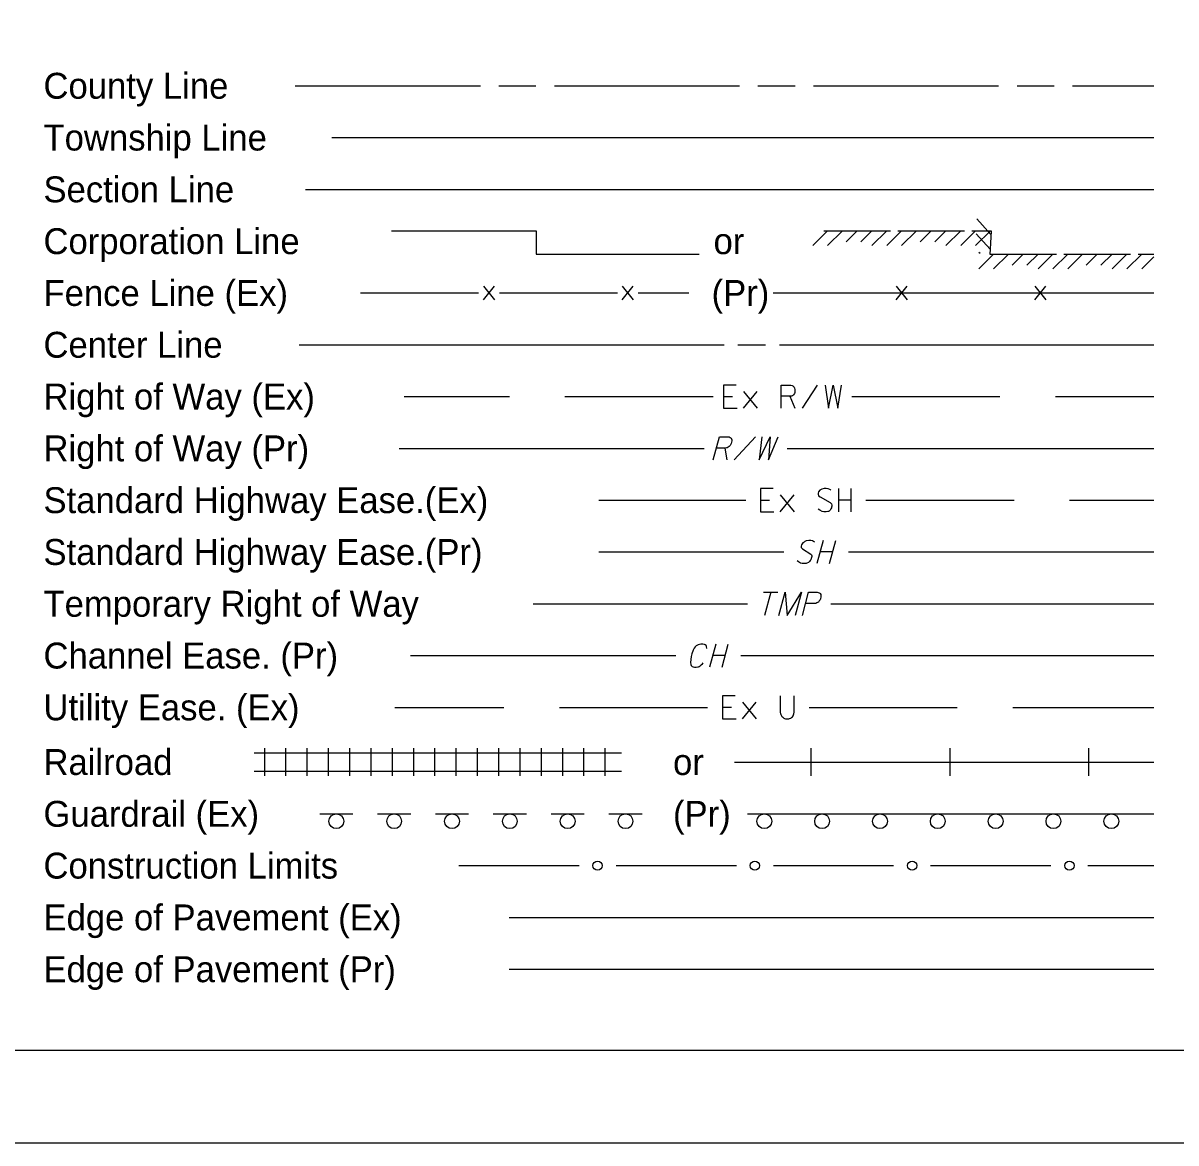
# Model space of a CAD drawing. Extents: x -19 to 40.8, y -1.8 to 26.1.
# Drawn here: x 1.61 to 7.84, y 0 to 6.05 of the extents above; entities that cross this region are included whole.
import ezdxf

# ---------------------------------------------------------------- set-up
doc = ezdxf.new("R2010")
doc.units = 0
for name, color, linetype in [('SH_Border', 7, 'Continuous'), ('SH_Cut_Line', 7, 'Continuous'), ('SH_Text', 7, 'Continuous')]:
    doc.layers.add(name, color=color, linetype=linetype)

msp = doc.modelspace()

# ---------------------------------------------------------------- linework, layer by layer
at = {"layer": 'SH_Border'}
msp.add_lwpolyline([(1.5, 21.5), (33.5, 21.5), (33.5, 0.5), (1.5, 0.5)], close=True, dxfattribs=at)
at = {"layer": 'SH_Cut_Line'}
msp.add_lwpolyline([(0, 0), (34, 0), (34, 22), (0, 22)], close=True, dxfattribs=at)
at = {"layer": 'SH_Text'}
for p, q in [((3.0856, 5.7144), (4.0856, 5.7144)), ((4.1856, 5.7144), (4.3856, 5.7144)), ((4.4856, 5.7144), (5.4856, 5.7144)), ((5.5856, 5.7144), (5.7856, 5.7144)), ((5.8856, 5.7144), (6.8856, 5.7144)), ((6.9856, 5.7144), (7.1856, 5.7144)), ((7.2856, 5.7144), (7.7247, 5.7144)), ((3.2837, 5.4344), (7.7247, 5.4344)), ((3.141, 5.1544), (7.7247, 5.1544)), ((6.844, 4.9108), (6.7678, 4.9945)), ((3.6051, 4.9308), (4.3876, 4.9308)), ((4.3876, 4.9308), (4.3876, 4.8044)), ((5.9614, 4.9308), (5.8814, 4.8508)), ((5.9414, 4.9308), (6.0414, 4.9308)), ((6.0414, 4.9308), (5.9614, 4.8508)), ((6.0414, 4.9308), (6.1214, 4.9308)), ((6.1214, 4.9308), (6.0614, 4.8708)), ((6.1214, 4.9308), (6.2014, 4.9308)), ((6.2014, 4.9308), (6.1414, 4.8708)), ((6.2014, 4.9308), (6.3014, 4.9308)), ((6.2814, 4.9308), (6.2014, 4.8508)), ((6.3614, 4.9308), (6.2814, 4.8508)), ((6.3414, 4.9308), (6.4414, 4.9308)), ((6.4414, 4.9308), (6.3614, 4.8508)), ((6.4414, 4.9308), (6.5214, 4.9308)), ((6.5214, 4.9308), (6.4614, 4.8708)), ((6.5214, 4.9308), (6.6014, 4.9308)), ((6.6014, 4.9308), (6.5414, 4.8708)), ((6.6014, 4.9308), (6.7014, 4.9308)), ((6.6814, 4.9308), (6.6014, 4.8508)), ((6.7614, 4.9308), (6.6814, 4.8508)), ((6.7414, 4.9308), (6.8414, 4.9308)), ((6.8414, 4.9308), (6.7614, 4.8508)), ((6.8449, 4.9308), (6.8403, 4.8309)), ((6.8414, 4.9308), (6.8449, 4.9308)), ((6.8403, 4.8309), (6.7641, 4.9145)), ((4.3876, 4.8044), (5.2686, 4.8044)), ((6.859, 4.8044), (6.779, 4.7244)), ((6.7857, 4.8069), (6.7794, 4.8137)), ((6.8403, 4.8309), (6.839, 4.8044)), ((6.839, 4.8044), (6.939, 4.8044)), ((6.939, 4.8044), (6.859, 4.7244)), ((6.939, 4.8044), (7.019, 4.8044)), ((7.019, 4.8044), (6.959, 4.7444)), ((7.019, 4.8044), (7.099, 4.8044)), ((7.099, 4.8044), (7.039, 4.7444)), ((7.099, 4.8044), (7.199, 4.8044)), ((7.179, 4.8044), (7.099, 4.7244)), ((7.259, 4.8044), (7.179, 4.7244)), ((7.239, 4.8044), (7.339, 4.8044)), ((7.339, 4.8044), (7.259, 4.7244)), ((7.339, 4.8044), (7.419, 4.8044)), ((7.419, 4.8044), (7.359, 4.7444)), ((7.419, 4.8044), (7.499, 4.8044)), ((7.499, 4.8044), (7.439, 4.7444)), ((7.499, 4.8044), (7.599, 4.8044)), ((7.579, 4.8044), (7.499, 4.7244)), ((7.659, 4.8044), (7.579, 4.7244)), ((7.639, 4.8044), (7.7247, 4.8044)), ((7.7247, 4.79), (7.659, 4.7244)), ((4.1022, 4.5569), (4.1615, 4.6319)), ((4.1022, 4.6319), (4.1616, 4.5569)), ((4.8522, 4.5569), (4.9115, 4.6319)), ((4.8522, 4.6319), (4.9116, 4.5569)), ((6.3322, 4.5569), (6.3915, 4.6319)), ((6.3322, 4.6319), (6.3916, 4.5569)), ((7.0822, 4.5569), (7.1415, 4.6319)), ((7.0822, 4.6319), (7.1416, 4.5569)), ((3.4381, 4.5944), (4.0756, 4.5944)), ((4.1881, 4.5944), (4.8256, 4.5944)), ((4.9381, 4.5944), (5.2112, 4.5944)), ((5.6682, 4.5944), (7.7247, 4.5944)), ((3.1065, 4.3144), (5.402, 4.3144)), ((5.477, 4.3144), (5.552, 4.3144)), ((5.552, 4.3144), (5.627, 4.3144)), ((5.702, 4.3144), (7.7247, 4.3144)), ((5.5066, 4.0624), (5.5814, 3.9719)), ((5.5066, 3.9719), (5.5814, 4.0624)), ((5.8255, 3.9719), (5.9072, 4.0969)), ((3.6741, 4.0344), (4.2426, 4.0344)), ((4.5426, 4.0344), (5.3426, 4.0344)), ((5.3993, 4.0349), (5.4476, 4.0349)), ((5.7576, 4.0358), (5.7851, 3.9719)), ((6.0926, 4.0344), (6.8926, 4.0344)), ((7.1926, 4.0344), (7.7247, 4.0344)), ((5.4576, 3.6919), (5.5728, 3.8169)), ((3.6463, 3.7544), (4.2941, 3.7544)), ((4.2941, 3.7544), (5.2941, 3.7544)), ((5.4064, 3.7558), (5.4173, 3.6919)), ((5.7441, 3.7544), (7.7247, 3.7544)), ((5.7063, 3.5024), (5.7811, 3.4119)), ((5.7063, 3.4119), (5.7811, 3.5024)), ((6.0213, 3.5369), (6.0213, 3.4119)), ((6.0892, 3.4119), (6.0892, 3.5369)), ((4.7247, 3.4744), (5.5191, 3.4744)), ((5.5991, 3.4749), (5.6473, 3.4749)), ((6.0892, 3.4749), (6.0213, 3.4749)), ((6.1691, 3.4744), (6.9691, 3.4744)), ((7.2691, 3.4744), (7.7247, 3.4744)), ((5.9376, 3.2569), (5.9041, 3.1319)), ((5.972, 3.1319), (6.0055, 3.2569)), ((4.7247, 3.1944), (5.7247, 3.1944)), ((5.9887, 3.1949), (5.9208, 3.1949)), ((6.0747, 3.1944), (7.7247, 3.1944)), ((5.6147, 2.9769), (5.6925, 2.9769)), ((5.6541, 2.9769), (5.6206, 2.8519)), ((4.3701, 2.9144), (4.5285, 2.9144)), ((4.5285, 2.9144), (5.5285, 2.9144)), ((5.9785, 2.9144), (7.7247, 2.9144)), ((5.357, 2.6969), (5.3235, 2.5719)), ((5.3914, 2.5719), (5.4249, 2.6969)), ((3.7075, 2.6344), (4.142, 2.6344)), ((4.142, 2.6344), (5.142, 2.6344)), ((5.4081, 2.6349), (5.3402, 2.6349)), ((5.492, 2.6344), (7.7247, 2.6344)), ((5.5016, 2.3824), (5.5764, 2.2919)), ((5.5016, 2.2919), (5.5764, 2.3824)), ((3.624, 2.3544), (4.2127, 2.3544)), ((4.5127, 2.3544), (5.3127, 2.3544)), ((5.3944, 2.3549), (5.4426, 2.3549)), ((5.8627, 2.3544), (6.6627, 2.3544)), ((6.9627, 2.3544), (7.7247, 2.3544)), ((2.9202, 1.984), (2.9202, 2.134)), ((3.0352, 1.984), (3.0352, 2.134)), ((3.1502, 1.984), (3.1502, 2.134)), ((3.2652, 1.984), (3.2652, 2.134)), ((3.3802, 1.984), (3.3802, 2.134)), ((3.4952, 1.984), (3.4952, 2.134)), ((3.6102, 1.984), (3.6102, 2.134)), ((3.7252, 1.984), (3.7252, 2.134)), ((3.8402, 1.984), (3.8402, 2.134)), ((3.9552, 1.984), (3.9552, 2.134)), ((4.0702, 1.984), (4.0702, 2.134)), ((4.1852, 1.984), (4.1852, 2.134)), ((4.3002, 1.984), (4.3002, 2.134)), ((4.4152, 1.984), (4.4152, 2.134)), ((4.5302, 1.984), (4.5302, 2.134)), ((4.6452, 1.984), (4.6452, 2.134)), ((4.7602, 1.984), (4.7602, 2.134)), ((5.8738, 1.984), (5.8738, 2.134)), ((6.6238, 1.984), (6.6238, 2.134)), ((7.3738, 1.984), (7.3738, 2.134)), ((2.8627, 2.109), (4.8489, 2.109)), ((5.4584, 2.059), (7.7247, 2.059)), ((2.8627, 2.009), (4.8489, 2.009)), ((3.2172, 1.779), (3.3972, 1.779)), ((3.5297, 1.779), (3.7097, 1.779)), ((3.8422, 1.779), (4.0222, 1.779)), ((4.1547, 1.779), (4.3347, 1.779)), ((4.4672, 1.779), (4.6472, 1.779)), ((4.7797, 1.779), (4.9597, 1.779)), ((5.5295, 1.779), (7.7247, 1.779)), ((3.9686, 1.499), (4.6186, 1.499)), ((4.8186, 1.499), (5.4686, 1.499)), ((5.6686, 1.499), (6.3186, 1.499)), ((6.5186, 1.499), (7.1686, 1.499)), ((7.3686, 1.499), (7.7247, 1.499)), ((4.2413, 1.219), (7.7247, 1.219)), ((4.2413, 0.939), (7.7247, 0.939))]:
    msp.add_line(p, q, dxfattribs=at)
for points in [[(5.4673, 4.0969), (5.3993, 4.0969), (5.3993, 3.9719), (5.4722, 3.9719)], [(5.7113, 3.9719), (5.7113, 4.0969), (5.7586, 4.0969), (5.7635, 4.0959), (5.7704, 4.0939), (5.7733, 4.0919), (5.7763, 4.09), (5.7802, 4.0851), (5.7832, 4.0801), (5.7851, 4.0723), (5.7851, 4.0604), (5.7841, 4.0565), (5.7822, 4.0506), (5.7782, 4.0437), (5.7743, 4.0408), (5.7714, 4.0388), (5.7694, 4.0378), (5.7664, 4.0368), (5.7576, 4.0358), (5.7113, 4.0358)], [(5.9485, 4.0969), (5.9672, 3.9719), (5.9918, 4.0969), (6.0164, 3.9719), (6.0361, 4.0969)], [(5.3434, 3.6919), (5.3769, 3.8169), (5.4241, 3.8169), (5.4291, 3.8159), (5.435, 3.8139), (5.4379, 3.8119), (5.4399, 3.81), (5.4428, 3.8051), (5.4438, 3.8001), (5.4438, 3.7952), (5.4428, 3.7873), (5.4409, 3.7804), (5.4389, 3.7765), (5.435, 3.7706), (5.43, 3.7637), (5.4251, 3.7608), (5.4212, 3.7588), (5.4192, 3.7578), (5.4163, 3.7568), (5.4064, 3.7558), (5.3602, 3.7558)], [(5.6072, 3.8169), (5.5924, 3.6919), (5.6505, 3.8169), (5.6416, 3.6919), (5.6948, 3.8169)], [(5.667, 3.5369), (5.5991, 3.5369), (5.5991, 3.4119), (5.6719, 3.4119)], [(5.979, 3.528), (5.977, 3.53), (5.974, 3.5319), (5.9652, 3.5349), (5.9544, 3.5369), (5.9465, 3.5369), (5.9435, 3.5369), (5.9307, 3.5339), (5.9199, 3.528), (5.913, 3.5201), (5.911, 3.5123), (5.911, 3.5064), (5.913, 3.4985), (5.9209, 3.4916), (5.975, 3.4621), (5.9799, 3.4581), (5.9819, 3.4542), (5.9839, 3.4483), (5.9839, 3.4424), (5.9829, 3.4365), (5.9819, 3.4325), (5.9799, 3.4276), (5.978, 3.4237), (5.976, 3.4207), (5.9731, 3.4178), (5.9701, 3.4158), (5.9662, 3.4138), (5.9632, 3.4129), (5.9544, 3.4119), (5.9406, 3.4119), (5.9317, 3.4138), (5.9189, 3.4207), (5.911, 3.4266)], [(5.8933, 3.248), (5.8864, 3.2519), (5.8805, 3.2549), (5.8706, 3.2569), (5.8628, 3.2569), (5.8598, 3.2569), (5.846, 3.2539), (5.8391, 3.251), (5.8342, 3.248), (5.8273, 3.2431), (5.8234, 3.2392), (5.8204, 3.2323), (5.8194, 3.2264), (5.8194, 3.2185), (5.8254, 3.2116), (5.8716, 3.1821), (5.8756, 3.1781), (5.8765, 3.1742), (5.8765, 3.1703), (5.8756, 3.1653), (5.8736, 3.1594), (5.8726, 3.1565), (5.8706, 3.1525), (5.8667, 3.1476), (5.8637, 3.1437), (5.8578, 3.1378), (5.85, 3.1338), (5.846, 3.1329), (5.8372, 3.1319), (5.8234, 3.1319), (5.8155, 3.1338), (5.8037, 3.1407), (5.7978, 3.1466)], [(5.6984, 2.8519), (5.7318, 2.9769), (5.7437, 2.8519), (5.8204, 2.9769), (5.787, 2.8519)], [(5.8254, 2.8519), (5.8588, 2.9769), (5.9061, 2.9769), (5.911, 2.9759), (5.9169, 2.9739), (5.9198, 2.9719), (5.9218, 2.97), (5.9248, 2.9651), (5.9257, 2.9601), (5.9257, 2.9523), (5.9228, 2.9404), (5.9208, 2.9365), (5.9169, 2.9306), (5.912, 2.9237), (5.907, 2.9208), (5.9031, 2.9188), (5.8982, 2.9168), (5.8893, 2.9158), (5.8421, 2.9158)], [(5.3097, 2.6723), (5.3078, 2.6831), (5.3048, 2.689), (5.3009, 2.6929), (5.2969, 2.6949), (5.2871, 2.6969), (5.2763, 2.6969), (5.2615, 2.6929), (5.2517, 2.687), (5.2467, 2.6821), (5.2408, 2.6752), (5.2349, 2.6644), (5.229, 2.6447), (5.2251, 2.6299), (5.2211, 2.5975), (5.2221, 2.5856), (5.2241, 2.5807), (5.23, 2.5758), (5.2359, 2.5738), (5.2428, 2.5719), (5.2517, 2.5719), (5.2605, 2.5729), (5.2645, 2.5738), (5.2684, 2.5758), (5.2733, 2.5797), (5.2792, 2.5847), (5.2851, 2.5906), (5.2891, 2.5955)], [(5.4623, 2.4169), (5.3944, 2.4169), (5.3944, 2.2919), (5.4672, 2.2919)], [(5.7063, 2.4169), (5.7063, 2.3293), (5.7073, 2.3204), (5.7083, 2.3175), (5.7103, 2.3125), (5.7122, 2.3086), (5.7152, 2.3047), (5.7172, 2.3027), (5.7181, 2.3017), (5.7221, 2.2988), (5.725, 2.2968), (5.729, 2.2948), (5.7349, 2.2929), (5.7408, 2.2919), (5.7467, 2.2919), (5.7526, 2.2929), (5.7565, 2.2938), (5.7624, 2.2968), (5.7673, 2.2997), (5.7713, 2.3037), (5.7752, 2.3086), (5.7782, 2.3145), (5.7801, 2.3194), (5.7811, 2.3293), (5.7811, 2.4169)]]:
    msp.add_lwpolyline(points, dxfattribs=at)
for centre, radius in [((3.3072, 1.739), 0.04), ((3.6197, 1.739), 0.04), ((3.9322, 1.739), 0.04), ((4.2447, 1.739), 0.04), ((4.5572, 1.739), 0.04), ((4.8697, 1.739), 0.04), ((5.6195, 1.739), 0.04), ((5.932, 1.739), 0.04), ((6.2445, 1.739), 0.04), ((6.557, 1.739), 0.04), ((6.8695, 1.739), 0.04), ((7.182, 1.739), 0.04), ((7.4945, 1.739), 0.04), ((4.7186, 1.499), 0.025), ((5.5686, 1.499), 0.025), ((6.4186, 1.499), 0.025), ((7.2686, 1.499), 0.025)]:
    msp.add_circle(centre, radius, dxfattribs=at)

# ---------------------------------------------------------------- texts
for s, p in [('County Line', (1.7247, 5.6444)), ('Township Line', (1.7247, 5.3644)), ('Section Line', (1.7247, 5.0844)), ('Corporation Line                                           or', (1.7247, 4.8044)), ('Fence Line (Ex)                                            (Pr)', (1.7247, 4.5244)), ('Center Line', (1.7247, 4.2444)), ('Right of Way (Ex)', (1.7247, 3.9644)), ('Right of Way (Pr)', (1.7247, 3.6844)), ('Standard Highway Ease.(Ex)', (1.7247, 3.4044)), ('Standard Highway Ease.(Pr)', (1.7247, 3.1244)), ('Temporary Right of Way', (1.7247, 2.8444)), ('Channel Ease. (Pr)', (1.7247, 2.5644)), ('Utility Ease. (Ex)', (1.7247, 2.2844)), ('Railroad                                                    or', (1.7247, 1.989)), ('Guardrail (Ex)                                           (Pr)', (1.7247, 1.709)), ('Construction Limits', (1.7247, 1.429)), ('Edge of Pavement (Ex)', (1.7247, 1.149)), ('Edge of Pavement (Pr)', (1.7247, 0.869))]:
    msp.add_text(s, height=0.14, dxfattribs=at).set_placement(p)

doc.saveas('drawing.dxf')
